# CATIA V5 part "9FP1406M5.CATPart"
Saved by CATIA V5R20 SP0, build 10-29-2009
Part number: 9FP1406M5
Revision: ANY
Definition: UNKNOWN
Nomenclature: 9FP1406M5
Source: Unknown
Bounding box of the stored display mesh (mm): x -6.727 to 6.727, y 0 to 6, z -6.9 to 6.9
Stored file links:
  C:\Users\Utente\Desktop\IO LAVORO\3D X SITO CF\CUMSA\3D files PW\pw081025\pw081025_ejection\9FP1406M5.CATPart
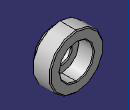
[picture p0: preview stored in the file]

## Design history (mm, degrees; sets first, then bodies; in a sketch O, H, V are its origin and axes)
Body1 "Chaflán1" (main body)
  Solid1: solid without history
